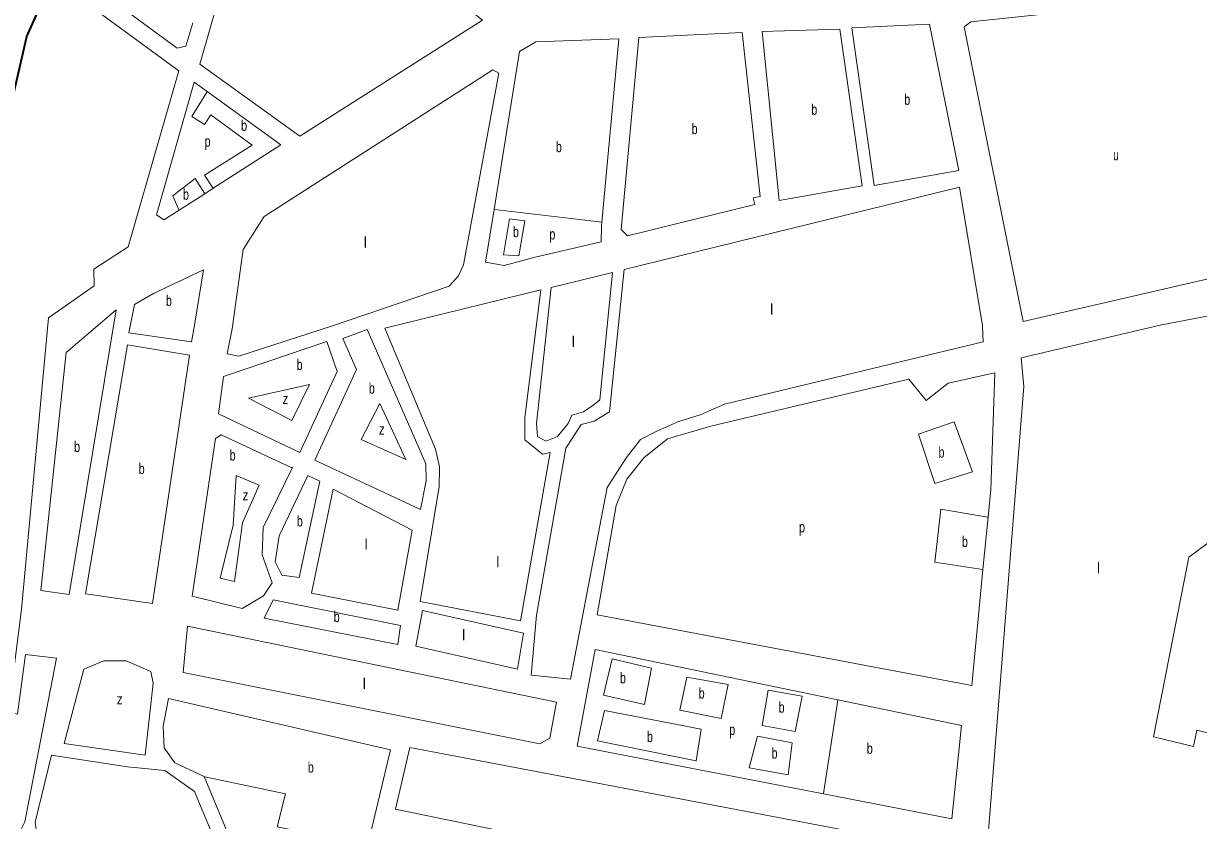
# Model space of a CAD drawing. Extents: x 639657 to 671642, y 222838 to 252123.
# Drawn here: x 648074 to 649169, y 235539 to 236282 of the extents above; entities that cross this region are included whole.
import ezdxf

# ---------------------------------------------------------------- set-up
doc = ezdxf.new("R2010")
doc.units = 0
doc.header["$LTSCALE"] = 4
for name, color, linetype, lineweight in [('1', 7, 'Continuous', 13), ('21', 7, 'Continuous', 13), ('57', 7, 'Continuous', 35)]:
    doc.layers.add(name, color=color, linetype=linetype, lineweight=lineweight)
doc.layers.add('7', color=7, linetype='Continuous')

msp = doc.modelspace()

# ---------------------------------------------------------------- linework, layer by layer
at = {"layer": '1'}
for p, q in [((648622.979, 236049.684), (648566.019, 236035.692)), ((648565.027, 235881.917), (648537.4, 235724.925)), ((648579.564, 235885.816), (648552.185, 235730.232)), ((648416.17, 235604.77), (648394.967, 235516.148))]:
    msp.add_line(p, q, dxfattribs=at)
for points in [[(648238.56, 236243.84), (648331.62, 236176.53), (648501.84, 236284.56), (648312.35, 236433.56), (648291.14, 236426.91)], [(649211.77, 236051.33), (649200.52, 236190.58), (649195.28, 236199.35), (649206.93, 236216.23), (649295.793, 236324.572), (649154.49, 236304.35), (648956.78, 236283.17), (648950.81, 236278.38), (649005.5, 236003.83)], [(648743.92, 236273.25), (648760.67, 236120.49), (648754.24, 236119.14), (648755.59, 236112.92), (648637.04, 236083.65), (648630.96, 236089.61), (648647.48, 236268.7)], [(648855.77, 236130.19), (648834.79, 236276.45), (648762.39, 236274.28), (648778.33, 236116.57)], [(648945.67, 236144.57), (648918.34, 236280.88), (648845.95, 236277.42), (648866.94, 236130.72)], [(648362.15, 235999.81), (648470.95, 236036.95), (648479.67, 236046.28), (648484.08, 236056.64), (648517.15, 236235.45), (648511.53, 236238.41), (648298.4, 236101.81), (648278.93, 236070.87), (648268.63, 235997.06), (648264.03, 235973.83), (648275.03, 235971.58)], [(648233.63, 236000.34), (648241.94, 236052.04), (648195.31, 236029.88), (648177.57, 236019.83), (648172.56, 235993.32), (648230.65, 235984.83)], [(648160.71, 236014.86), (648116.78, 235749.55), (648090.32, 235753.06), (648113.99, 235974.93)], [(649208.83, 235999.69), (649211.04, 236015.4), (649133.23, 236000.51), (649003.92, 235970.02), (649006.22, 235943.15), (648972.92, 235525.31), (649458.84, 235428.24), (649485.06, 235542.59), (649167.33, 235622.96), (649164.19, 235607.67), (649126.95, 235616.71), (649159.96, 235784.22), (649185, 235802.85)], [(648371.64, 235987.98), (648384.49, 235959.24), (648345.85, 235874.5), (648444.13, 235828.6), (648449.56, 235855.51), (648449.04, 235871.21), (648394.38, 235996.5)], [(648228.79, 235972.34), (648194.42, 235741.17), (648132.04, 235750.07), (648171.12, 235982.13)], [(648356.82, 235985.11), (648260.5, 235952.52), (648255.97, 235917.66), (648331.83, 235881.73), (648366.44, 235957.2)], [(648323.74, 235867.93), (648258.44, 235898.1), (648253.3, 235894.84), (648231.57, 235747.83), (648278.07, 235736.48), (648297.77, 235748.2), (648306.09, 235760.29), (648296.7, 235786.26), (648297.63, 235811.86), (648325.04, 235867.72)], [(648339.05, 235860.48), (648350.26, 235854.95), (648331.21, 235765.17), (648314.86, 235767.44), (648308.77, 235779.88), (648312.5, 235804.2)], [(648422.95, 235734.92), (648436.5, 235809.41), (648362.77, 235847.5), (648342.47, 235750.82)], [(648306.82, 235744.6), (648298.54, 235727.35), (648423.14, 235702.88), (648425.4, 235720.53)], [(648445.974, 235734.444), (648439.931, 235701.195), (648534.662, 235679.83), (648540.138, 235713.247)], [(648222.95, 235676.81), (648555.43, 235610.28), (648564.64, 235615.5), (648570.88, 235649.09), (648227.05, 235719.91)], [(648112.024, 235610.632), (648187.498, 235599.845), (648195.164, 235666.681), (648192.974, 235677.637), (648169.976, 235687.498), (648149.168, 235687.498), (648130.55, 235679.829)], [(648434.236, 235606.72), (648420.767, 235549.447), (648939.87, 235442.071), (648937.679, 235511.098)]]:
    msp.add_lwpolyline(points, close=True, dxfattribs=at)
for points in [[(648125.935, 236322.695), (648119.36, 236324.46), (648113.87, 236314.73), (648219.07, 236237.64), (648171.68, 236073.32), (648139.86, 236052.6), (648140.01, 236037.11), (648097.67, 236007.21), (648072.36, 235735.76), (648060.22, 235639.98), (648068.62, 235637.88), (648076.25, 235693.63), (648105.08, 235690.13), (648075.64, 235537.49), (648070.11, 235527.13), (648098.499, 235356.253)], [(648231.905, 236282.345), (648225.5, 236260.49), (648217.57, 236258.48), (648132.51, 236320.93), (648125.935, 236322.695)], [(648536.51, 236255.41), (648551.68, 236264.37), (648628.79, 236267.45), (648613.23, 236096.509)], [(648613.23, 236096.509), (648612.88, 236092.67), (648612.418, 236078.105), (648551.06, 236063.71), (648522.12, 236055.92), (648504.69, 236059.2), (648512.638, 236108.211), (648536.51, 236255.41)], [(648245.462, 236218.089), (648233.14, 236227.01), (648198.25, 236103.25)], [(648251.104, 236128.032), (648314.08, 236168.41), (648245.462, 236218.089)], [(648967.85, 235999.71), (648946.26, 236129.09), (648633.79, 236052.339)], [(648198.25, 236103.25), (648205.17, 236098.58), (648219.188, 236107.568), (648243.092, 236122.895), (648251.104, 236128.032)], [(648633.79, 236052.339), (648620.085, 235919.782), (648605.848, 235911.017), (648593.801, 235907.73), (648586.135, 235895.677), (648579.564, 235885.816)], [(648566.019, 236035.692), (648552.185, 235908.825), (648553.28, 235896.773), (648560.946, 235892.39), (648571.898, 235896.773), (648581.754, 235908.825), (648585.04, 235916.495), (648595.991, 235919.782), (648605.848, 235926.356), (648611.323, 235930.739), (648622.979, 236049.684)], [(648556.244, 236033.292), (648411.02, 235997.62), (648458.21, 235884.81), (648461.96, 235868.48), (648461.63, 235849.99), (648443.76, 235743), (648537.4, 235724.925)], [(648565.027, 235881.917), (648557.661, 235880.338), (648541.233, 235893.486), (648541.233, 235914.304), (648556.244, 236033.292)], [(648552.185, 235730.232), (648547.33, 235674.33), (648583.89, 235670.45), (648618.12, 235849.14), (648636.02, 235876.99), (648649.04, 235893.84), (648664.25, 235901.66), (648683.76, 235910.37), (648704.58, 235916.94), (648727.31, 235926.75), (648968.37, 235984.88), (648967.85, 235999.71)], [(648968.181, 235772.755), (648957.73, 235664.58), (648608.7, 235730.59), (648626.6, 235832.42), (648636.35, 235856.99), (648652.36, 235876.65), (648674.18, 235894.41), (648714.53, 235906.25), (648899.13, 235950.08), (648915.37, 235930.17), (648935.66, 235946.29), (648979.295, 235955.939)], [(648979.295, 235955.939), (648975.38, 235847.27), (648972.891, 235821.509), (648968.181, 235772.755)], [(648833.039, 235651.297), (648606.95, 235698.32), (648590.26, 235608.11), (648819.644, 235563.579), (648939.09, 235540.39)], [(648242.63, 235579.71), (648215.26, 235592.68), (648205.29, 235606.6), (648204.32, 235626.6), (648209.33, 235652.43), (648416.17, 235604.77)], [(648939.09, 235540.39), (648948.27, 235627.33), (648833.039, 235651.297)], [(648116.515, 235320.079), (648085.1, 235537.11), (648100.44, 235599.78), (648171.22, 235588.78), (648206.06, 235585.53), (648233.47, 235565.9), (648346.36, 235294.69), (648338.424, 235264.736)], [(648381.795, 235305.849), (648372.35, 235298.06), (648357.92, 235302.92), (648242.63, 235579.71)]]:
    msp.add_lwpolyline(points, dxfattribs=at)
at = {"layer": '21'}
for points in [[(648245.462, 236218.089), (648245.154, 236217.589), (648231.188, 236194.884), (648243.011, 236187.491), (648248.923, 236196.363), (648287.347, 236168.27), (648243.011, 236140.177), (648250.771, 236128.532), (648251.104, 236128.032)], [(648243.092, 236122.895), (648242.78, 236123.395), (648234.144, 236137.22), (648213.453, 236120.955), (648218.974, 236108.068), (648219.188, 236107.568)], [(648613.23, 236096.509), (648608.229, 236097.091), (648513.138, 236108.153), (648512.638, 236108.211)], [(648972.891, 235821.509), (648972.391, 235821.592), (648928.918, 235828.841), (648923.442, 235779.536), (648967.681, 235772.831), (648968.181, 235772.755)], [(648833.039, 235651.297), (648832.963, 235650.797), (648819.72, 235564.079), (648819.644, 235563.579)], [(648242.63, 235579.71), (648243.13, 235579.604), (648318.368, 235563.687), (648310.702, 235533.008), (648394.467, 235516.248), (648394.967, 235516.148)]]:
    msp.add_lwpolyline(points, dxfattribs=at)
for points in [[(648526.931, 236099.615), (648521.52, 236066.052), (648535.757, 236064.957), (648541.233, 236097.826)], [(648340.622, 235945.285), (648324.393, 235911.563), (648283.872, 235932.381)], [(648406.36, 235927.597), (648430.623, 235875.406), (648389.007, 235894.033)], [(648941.444, 235910.508), (648958.487, 235863.903), (648923.442, 235852.946), (648908.11, 235898.964)], [(648272.354, 235860.305), (648293.728, 235851.302), (648278.396, 235816.24), (648270.73, 235761.457), (648257.588, 235764.744), (648269.635, 235814.049)], [(648622.737, 235689.416), (648614.609, 235655.726), (648652.939, 235646.961), (648659.51, 235680.926)], [(648692.201, 235672.464), (648685.794, 235641.483), (648724.124, 235633.813), (648730.695, 235665.587)], [(648767.938, 235660.155), (648762.455, 235627.239), (648793.119, 235621.761), (648799.69, 235654.631)], [(648615.554, 235641.259), (648609.133, 235612.995), (648701.126, 235594.369), (648705.507, 235623.952)], [(648790.291, 235611.18), (648786.548, 235581.221), (648750.408, 235587.795), (648758.074, 235617.378)]]:
    msp.add_lwpolyline(points, close=True, dxfattribs=at)
at = {"layer": '57'}
msp.add_lwpolyline([(648056.694, 236178.651), (648077.383, 236269.56), (648113.411, 236350.225), (648154.274, 236405.789), (648201.05, 236442.66), (648258.986, 236472.731), (648333.334, 236490.803), (648424.501, 236508.623), (648540.719, 236532.049), (648638.396, 236553.637), (648749.723, 236570.284), (648832.114, 236583.501), (648926.736, 236588.164), (648991.288, 236584.772), (649073.136, 236556.912), (649237.676, 236515.501)], dxfattribs=at)

# ---------------------------------------------------------------- texts
at = {"layer": '7'}
for s, width, p in [('b', 0.75, (648808.254, 236196.51)), ('b', 0.75, (648894.795, 236205.8)), ('b', 0.75, (648277.002, 236181.577)), ('b', 0.75, (648696.735, 236178.45)), ('p', 0.75, (648243.011, 236166.791)), ('b', 0.75, (648570.236, 236161.685)), ('u', 0.7, (649089.518, 236154.09)), ('b', 0.75, (648222.887, 236117.329)), ('b', 0.75, (648530.282, 236082.487)), ('p', 0.75, (648564.231, 236080.296)), ('b', 0.75, (648206.922, 236018.435)), ('b', 0.75, (648328.679, 235958.62)), ('b', 0.75, (648396.007, 235936.654)), ('z', 0.8, (648315.631, 235926.903)), ('z', 0.8, (648405.434, 235898.415)), ('b', 0.75, (648121.421, 235882.205)), ('b', 0.75, (648266.35, 235874.311)), ('b', 0.75, (648926.728, 235877.051)), ('b', 0.75, (648181.582, 235861.65)), ('z', 0.8, (648278.396, 235837.058)), ('b', 0.75, (648328.945, 235812.825)), ('p', 0.75, (648796.855, 235807.33)), ('b', 0.75, (648948.631, 235793.78)), ('b', 0.75, (648363.254, 235723.74)), ('b', 0.75, (648629.941, 235666.683)), ('b', 0.75, (648703.316, 235652.439)), ('z', 0.8, (648161.214, 235646.959)), ('b', 0.75, (648777.787, 235639.291)), ('p', 0.75, (648731.79, 235618.474)), ('b', 0.75, (648655.13, 235611.9)), ('b', 0.75, (648771.216, 235596.56)), ('b', 0.75, (648859.923, 235600.943)), ('b', 0.75, (648339.176, 235583.409))]:
    msp.add_text(s, height=10, dxfattribs=dict(at, width=width)).set_placement(p)
for p in [(648391.197, 236072.626), (648769.898, 236010.343), (648585.04, 235980.043), (648392.07, 235791.21), (648514.727, 235774.775), (649074.351, 235769.297), (648482.967, 235706.844), (648390.427, 235661.374)]:
    msp.add_text('l', height=10, dxfattribs=at).set_placement(p)

doc.saveas('drawing.dxf')
